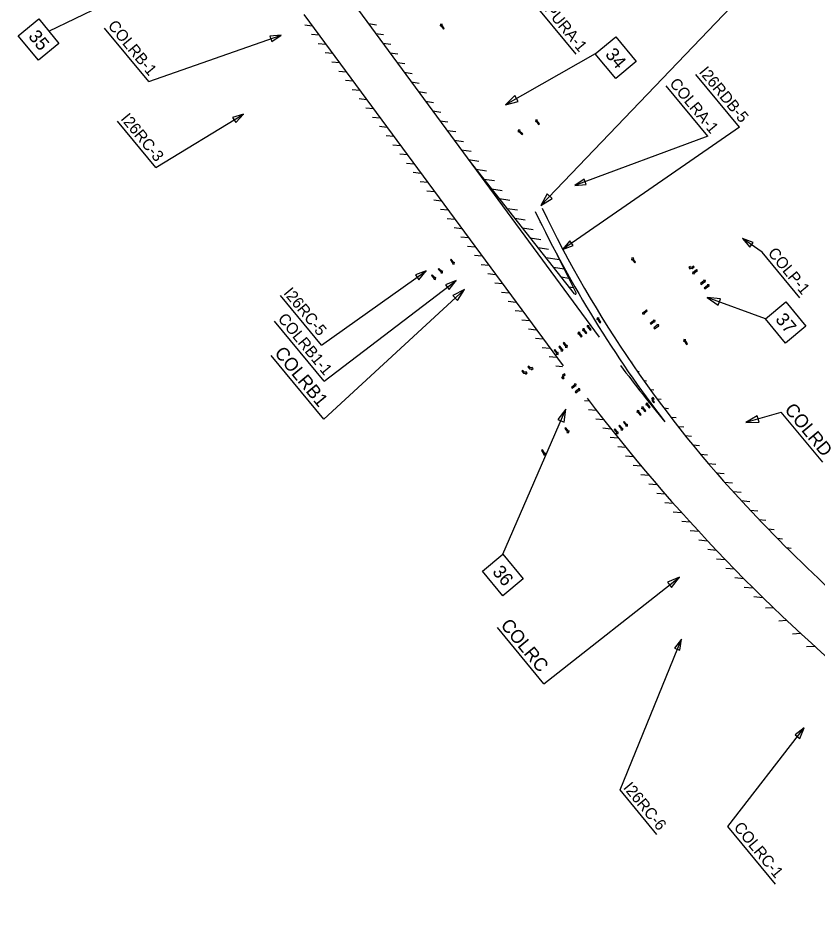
# Model space of a CAD drawing. Extents: x 1966356 to 1974207, y 790684 to 800034.
# Drawn here: x 1970016 to 1971705, y 794729 to 796663 of the extents above; entities that cross this region are included whole.
import ezdxf

# ---------------------------------------------------------------- set-up
doc = ezdxf.new("R2010")
doc.units = 0
doc.layers.add('RD_PD_ALT5_LnLine', color=7, linetype='Continuous')
doc.layers.add('RD_TX_RoadID', color=7, linetype='Continuous')

msp = doc.modelspace()

# ---------------------------------------------------------------- linework, layer by layer
at = {"layer": 'RD_PD_ALT5_LnLine'}
for p, q in [((1970581.2, 796888.4), (1971243.9, 795989.5)), ((1970619.8, 796670.9), (1971167.2, 795928.4)), ((1970621.4, 796648.6), (1970637.4, 796647)), ((1970756, 796651.3), (1970772.8, 796648.8)), ((1970635.7, 796629.1), (1970651.7, 796627.6)), ((1970771.1, 796630.8), (1970787.9, 796628.3)), ((1970650, 796609.7), (1970666.1, 796608.1)), ((1970786.2, 796610.4), (1970803, 796607.8)), ((1970664.4, 796590.2), (1970680.4, 796588.7)), ((1970801.3, 796589.9), (1970818.1, 796587.3)), ((1970678.7, 796570.8), (1970694.8, 796569.2)), ((1970693.1, 796551.3), (1970709.1, 796549.8)), ((1970816.4, 796569.4), (1970833.2, 796566.8)), ((1970707.4, 796531.8), (1970723.4, 796530.3)), ((1970831.5, 796548.9), (1970848.3, 796546.3)), ((1970846.6, 796528.4), (1970863.4, 796525.9)), ((1970721.8, 796512.4), (1970737.8, 796510.9)), ((1970861.7, 796507.9), (1970878.5, 796505.4)), ((1970736.1, 796492.9), (1970752.1, 796491.4)), ((1970876.8, 796487.4), (1970893.6, 796484.9)), ((1970750.4, 796473.5), (1970766.5, 796471.9)), ((1970891.9, 796466.9), (1970908.7, 796464.4)), ((1970764.8, 796454), (1970780.8, 796452.5)), ((1970907, 796446.4), (1970924.1, 796443.9)), ((1970779.1, 796434.6), (1970795.2, 796433)), ((1970922.1, 796425.9), (1970940.4, 796423.2)), ((1970793.5, 796415.1), (1970809.5, 796413.6)), ((1970937.2, 796405.5), (1970956.8, 796402.5)), ((1970807.8, 796395.7), (1970823.8, 796394.1)), ((1970952.3, 796385), (1970973.1, 796381.8)), ((1970822.1, 796376.2), (1970838.2, 796374.7)), ((1970967.5, 796364.5), (1970989.4, 796361.2)), ((1971191.7, 796080.5), (1970968.6, 796363)), ((1970836.5, 796356.8), (1970852.5, 796355.2)), ((1970983.7, 796343.8), (1971005.8, 796340.5)), ((1970850.8, 796337.3), (1970866.9, 796335.8)), ((1971000, 796323.1), (1971022.1, 796319.8)), ((1970865.2, 796317.8), (1970881.2, 796316.3)), ((1971016.4, 796302.5), (1971038.4, 796299.1)), ((1970879.5, 796298.4), (1970895.6, 796296.9)), ((1971032.7, 796281.8), (1971054.8, 796278.5)), ((1970893.9, 796278.9), (1970909.9, 796277.4)), ((1970908.2, 796259.5), (1970924.2, 796257.9)), ((1971049, 796261.1), (1971071.1, 796257.8)), ((1970922.5, 796240), (1970938.6, 796238.5)), ((1971065.4, 796240.4), (1971087.4, 796237.1)), ((1971118.4, 796232.4), (1971119.4, 796232.3)), ((1970936.9, 796220.6), (1970952.9, 796219)), ((1971081.7, 796219.8), (1971103.8, 796216.4)), ((1970951.2, 796201.1), (1970967.3, 796199.6)), ((1971098, 796199.1), (1971120.1, 796195.7)), ((1970965.6, 796181.7), (1970981.6, 796180.1)), ((1971114.4, 796178.4), (1971136.4, 796175.1)), ((1970979.9, 796162.2), (1970995.9, 796160.7)), ((1971130.7, 796157.7), (1971159.8, 796153.3)), ((1971195.1, 796082.7), (1971154.9, 796163.2)), ((1970994.2, 796142.8), (1971010.3, 796141.2)), ((1971147, 796137.1), (1971169.6, 796133.6)), ((1971008.6, 796123.3), (1971024.6, 796121.8)), ((1971163.4, 796116.4), (1971179.4, 796113.9)), ((1971022.9, 796103.8), (1971039, 796102.3)), ((1971179.7, 796095.7), (1971189.3, 796094.3)), ((1971037.3, 796084.4), (1971053.3, 796082.9)), ((1971051.6, 796064.9), (1971067.7, 796063.4)), ((1971066, 796045.5), (1971082, 796043.9)), ((1971080.3, 796026), (1971096.3, 796024.5)), ((1971094.6, 796006.6), (1971110.7, 796005)), ((1971109, 795987.1), (1971125, 795985.6)), ((1971123.3, 795967.7), (1971139.4, 795966.1)), ((1971137.7, 795948.2), (1971153.7, 795946.7)), ((1971310.7, 795936.5), (1971313.5, 795936.2)), ((1971152, 795928.8), (1971165.9, 795927.4)), ((1971324, 795917.2), (1971328.4, 795916.8)), ((1971337.6, 795897.8), (1971343.5, 795897.3)), ((1971351.5, 795878.5), (1971358.8, 795877.8)), ((1971212.4, 795855.5), (1971222.4, 795854.5)), ((1971365.7, 795859.1), (1971374.4, 795858.3)), ((1971221, 795836.5), (1971237.4, 795835)), ((1971380.1, 795839.7), (1971390.2, 795838.8)), ((1971236.2, 795817), (1971252.6, 795815.4)), ((1971394.9, 795820.3), (1971406.2, 795819.2)), ((1971251.5, 795797.5), (1971268.1, 795795.9)), ((1971410.1, 795800.8), (1971422.4, 795799.7)), ((1971267.1, 795777.9), (1971283.8, 795776.3)), ((1971425.5, 795781.3), (1971438.9, 795780.1)), ((1971441.3, 795761.8), (1971455.7, 795760.5)), ((1971282.9, 795758.3), (1971299.7, 795756.7)), ((1971457.5, 795742.2), (1971472.7, 795740.8)), ((1971298.9, 795738.7), (1971315.8, 795737.1)), ((1971474, 795722.6), (1971490, 795721.2)), ((1971315.2, 795719), (1971332.2, 795717.4)), ((1971490.9, 795703), (1971507.5, 795701.5)), ((1971331.7, 795699.4), (1971348.8, 795697.7)), ((1971508.1, 795683.3), (1971525.4, 795681.8)), ((1971348.4, 795679.7), (1971365.7, 795678)), ((1971525.8, 795663.6), (1971543.4, 795662)), ((1971365.4, 795660), (1971382.8, 795658.3)), ((1971543.9, 795643.9), (1971561.7, 795642.3)), ((1971382.7, 795640.3), (1971400.2, 795638.6)), ((1971562.4, 795624.1), (1971578.7, 795622.6)), ((1971400.2, 795620.5), (1971417.8, 795618.8)), ((1971581.2, 795604.3), (1971595.9, 795603)), ((1971418, 795600.7), (1971435.7, 795599)), ((1971436, 795580.9), (1971453.9, 795579.2)), ((1971600.4, 795584.5), (1971613.3, 795583.3)), ((1971454.3, 795561.1), (1971472.3, 795559.3)), ((1971619.8, 795564.6), (1971631, 795563.6)), ((1971472.9, 795541.2), (1971491.1, 795539.5)), ((1971639.6, 795544.7), (1971649.1, 795543.9)), ((1971491.8, 795521.3), (1971510.1, 795519.6)), ((1971659.7, 795524.8), (1971660, 795524.8)), ((1971511, 795501.4), (1971529.5, 795499.6)), ((1971530.5, 795481.4), (1971549.1, 795479.7)), ((1971550.3, 795461.5), (1971569.1, 795459.7)), ((1971570.4, 795441.5), (1971589.5, 795439.6)), ((1971595, 795417.5), (1971611.2, 795418.5)), ((1971623.4, 795390.2), (1971639.8, 795391.2)), ((1971652.4, 795362.9), (1971669, 795363.9)), ((1971682, 795335.7), (1971698.7, 795336.7))]:
    msp.add_line(p, q, dxfattribs=at)
for points in [[(1970914.3, 796639.9), (1970916.2, 796641.2), (1970911.1, 796648.8), (1970912.4, 796649.7), (1970908.5, 796650.5), (1970907.7, 796646.5), (1970909.1, 796647.4)], [(1971115.6, 796438), (1971117.5, 796439.4), (1971112.1, 796446.8), (1971113.5, 796447.8), (1971109.5, 796448.4), (1971108.9, 796444.5), (1971110.2, 796445.4)], [(1971080.5, 796417.2), (1971082.1, 796418.9), (1971075.4, 796425.2), (1971076.5, 796426.4), (1971072.5, 796426.2), (1971072.7, 796422.2), (1971073.8, 796423.4)], [(1970931.1, 796153.7), (1970929.2, 796152.3), (1970934.7, 796144.9), (1970933.4, 796144), (1970937.3, 796143.4), (1970937.9, 796147.3), (1970936.6, 796146.4)], [(1971318.7, 796146), (1971320.7, 796147.4), (1971315.5, 796154.9), (1971316.8, 796155.8), (1971312.9, 796156.5), (1971312.2, 796152.6), (1971313.5, 796153.5)], [(1970904.8, 796134.3), (1970903.1, 796132.5), (1970909.9, 796126.3), (1970908.8, 796125.1), (1970912.7, 796125.3), (1970912.6, 796129.3), (1970911.5, 796128.1)], [(1971444.4, 796137.4), (1971442.9, 796139.3), (1971439.5, 796136.6), (1971436.1, 796137), (1971436.3, 796138.6), (1971433.1, 796136.1), (1971435.6, 796133), (1971435.8, 796134.6), (1971440.3, 796134.1)], [(1971451.1, 796129.8), (1971449.6, 796131.7), (1971442.4, 796126), (1971441.4, 796127.3), (1971440.9, 796123.3), (1971444.9, 796122.8), (1971443.9, 796124.1)], [(1970890.9, 796121.1), (1970889.1, 796119.5), (1970895.2, 796112.6), (1970894, 796111.5), (1970898, 796111.3), (1970898.2, 796115.3), (1970897, 796114.2)], [(1971457.9, 796102.5), (1971459.4, 796100.6), (1971466.6, 796106.4), (1971467.6, 796105.1), (1971468.1, 796109.1), (1971464.1, 796109.5), (1971465.1, 796108.2)], [(1971465.6, 796092.9), (1971467.1, 796091), (1971474.3, 796096.7), (1971475.3, 796095.4), (1971475.8, 796099.4), (1971471.8, 796099.9), (1971472.8, 796098.6)], [(1971244.8, 796019.3), (1971246.9, 796020.6), (1971242.1, 796028.4), (1971243.4, 796029.2), (1971239.5, 796030.2), (1971238.6, 796026.3), (1971240, 796027.1)], [(1971345.3, 796044.7), (1971343.8, 796046.6), (1971336.7, 796040.9), (1971335.6, 796042.2), (1971335.2, 796038.2), (1971339.2, 796037.7), (1971338.2, 796039)], [(1971224.8, 796003.7), (1971226.7, 796005.2), (1971221.1, 796012.4), (1971222.3, 796013.4), (1971218.4, 796013.9), (1971217.9, 796010), (1971219.2, 796011)], [(1971351.4, 796018.2), (1971352.9, 796016.3), (1971360.1, 796022), (1971361.1, 796020.7), (1971361.6, 796024.7), (1971357.6, 796025.2), (1971358.6, 796023.9)], [(1971359.3, 796008.7), (1971360.8, 796006.8), (1971368, 796012.5), (1971369, 796011.3), (1971369.4, 796015.2), (1971365.5, 796015.7), (1971366.5, 796014.4)], [(1971205.5, 795989.5), (1971207.4, 795991), (1971201.8, 795998.2), (1971203.1, 795999.2), (1971199.1, 795999.7), (1971198.6, 795995.8), (1971199.9, 795996.8)], [(1971215.4, 795996.8), (1971217.3, 795998.3), (1971211.7, 796005.5), (1971212.9, 796006.5), (1971209, 796007), (1971208.5, 796003), (1971209.8, 796004)], [(1971169.7, 795977.9), (1971167.8, 795976.4), (1971173.3, 795969.1), (1971172, 795968.1), (1971176, 795967.6), (1971176.5, 795971.6), (1971175.2, 795970.6)], [(1971428.4, 795973.7), (1971430.4, 795975), (1971425.2, 795982.6), (1971426.5, 795983.5), (1971422.6, 795984.2), (1971421.8, 795980.3), (1971423.2, 795981.2)], [(1971150.2, 795963.2), (1971148.3, 795961.7), (1971153.9, 795954.4), (1971152.6, 795953.5), (1971156.6, 795952.9), (1971157.1, 795956.9), (1971155.8, 795955.9)], [(1971160.2, 795970.2), (1971158.3, 795968.8), (1971163.9, 795961.5), (1971162.6, 795960.5), (1971166.5, 795960), (1971167.1, 795963.9), (1971165.8, 795962.9)], [(1971080.5, 795917.3), (1971083.8, 795913.1), (1971088.3, 795912.6), (1971088.1, 795911), (1971091.2, 795913.5), (1971088.7, 795916.6), (1971088.6, 795915), (1971085.1, 795915.4), (1971082.4, 795918.8)], [(1971093, 795926.7), (1971096.4, 795922.5), (1971100.8, 795922), (1971100.6, 795920.4), (1971103.8, 795922.9), (1971101.3, 795926), (1971101.1, 795924.4), (1971097.6, 795924.8), (1971094.9, 795928.2)], [(1971170.4, 795911.6), (1971166.2, 795908.3), (1971165.7, 795903.8), (1971164.1, 795904), (1971166.6, 795900.9), (1971169.7, 795903.4), (1971168.1, 795903.6), (1971168.5, 795907), (1971171.9, 795909.8)], [(1971184.9, 795883.1), (1971186.4, 795881.2), (1971193.6, 795887), (1971194.6, 795885.7), (1971195, 795889.7), (1971191.1, 795890.1), (1971192.1, 795888.8)], [(1971192.8, 795873.6), (1971194.3, 795871.8), (1971201.4, 795877.5), (1971202.5, 795876.2), (1971202.9, 795880.2), (1971198.9, 795880.6), (1971199.9, 795879.4)], [(1971358.8, 795850.3), (1971360.7, 795851.8), (1971358, 795855.2), (1971358.4, 795858.7), (1971360, 795858.5), (1971357.6, 795861.6), (1971354.4, 795859.1), (1971356, 795858.9), (1971355.5, 795854.5)], [(1971340.1, 795832), (1971342, 795833.5), (1971336.3, 795840.6), (1971337.5, 795841.7), (1971333.6, 795842.1), (1971333.1, 795838.1), (1971334.4, 795839.1)], [(1971349.5, 795839.8), (1971351.4, 795841.3), (1971345.6, 795848.4), (1971346.9, 795849.4), (1971342.9, 795849.9), (1971342.5, 795845.9), (1971343.8, 795846.9)], [(1971330.4, 795824.2), (1971332.3, 795825.7), (1971326.6, 795832.9), (1971327.8, 795833.9), (1971323.9, 795834.4), (1971323.4, 795830.4), (1971324.7, 795831.4)], [(1971172.9, 795797.8), (1971171.1, 795796.3), (1971176.8, 795789.1), (1971175.5, 795788.1), (1971179.5, 795787.6), (1971179.9, 795791.6), (1971178.7, 795790.6)], [(1971286.8, 795803.5), (1971284.9, 795802), (1971290.7, 795794.8), (1971289.4, 795793.8), (1971293.4, 795793.4), (1971293.8, 795797.3), (1971292.6, 795796.3)], [(1971296.6, 795811.3), (1971294.7, 795809.8), (1971300.4, 795802.6), (1971299.2, 795801.6), (1971303.2, 795801.2), (1971303.6, 795805.2), (1971302.3, 795804.1)], [(1971277, 795795.7), (1971275.2, 795794.2), (1971280.9, 795787), (1971279.6, 795786), (1971283.6, 795785.5), (1971284, 795789.5), (1971282.8, 795788.5)], [(1971123.8, 795751.1), (1971121.7, 795749.9), (1971126.5, 795742), (1971125.1, 795741.2), (1971128.9, 795740.2), (1971129.9, 795744.1), (1971128.5, 795743.3)]]:
    msp.add_lwpolyline(points, close=True, dxfattribs=at)
for centre, radius, start, end in [((1973392.6, 797356.4), 2520, 205.75, 223.1722), ((1973392.6, 797356.4), 2536, 205.75, 217.5539), ((1971193.3, 796081.7), 2, 216.3977, 30.0977), ((1974296, 798203.9), 3770.7, 217.1065, 219.3969), ((1974296, 798203.9), 3868.7, 217.2903, 243.9112), ((1974296, 798203.9), 3758.7, 223.1722, 227.2191)]:
    msp.add_arc(centre, radius, start, end, dxfattribs=at)
at = {"layer": 'RD_TX_RoadID'}
for p, q in [((1971194.9, 796587), (1971065.8, 796743.3)), ((1970292, 796528.9), (1970198.5, 796642.1)), ((1971539.8, 796433), (1971447.9, 796544.2)), ((1971473.3, 796413.4), (1971385.5, 796519.9)), ((1970306.9, 796347.3), (1970225.8, 796445.4)), ((1971667.5, 796072.2), (1971587.7, 796168.8)), ((1970656.6, 795972.5), (1970569.9, 796077.4)), ((1970662.5, 795896.3), (1970557.8, 796023.2)), ((1970661.9, 795815.8), (1970550.5, 795950.7)), ((1971716.1, 795724.9), (1971628.4, 795831.1)), ((1971126.8, 795256.9), (1971028.5, 795375.8)), ((1971365.4, 794938.9), (1971287.8, 795032.9)), ((1971616, 794834.1), (1971515.6, 794955.7))]:
    msp.add_line(p, q, dxfattribs=at)
for points in [[(1970080.6, 796635.4), (1970303.3, 796743.1)], [(1971554.2, 796720.6), (1971120, 796267.5)], [(1970292, 796528.9), (1970571.4, 796626.9)], [(1971235.3, 796587.7), (1971045.5, 796479.6)], [(1970306.9, 796347.3), (1970492, 796459.9)], [(1971539.8, 796433), (1971166.3, 796174.4)], [(1971473.3, 796413.4), (1971192.3, 796309.3)], [(1971587.7, 796168.8), (1971546.4, 796197.4)], [(1970656.6, 795972.5), (1970878.2, 796129)], [(1970662.5, 795896.3), (1970941.1, 796108.9)], [(1970661.9, 795815.8), (1970958.8, 796090)], [(1971594.8, 796028), (1971471.9, 796072.8)], [(1971040, 795530.6), (1971173.5, 795837.3)], [(1971627.5, 795830.4), (1971553.7, 795808.9)], [(1971126.8, 795256.9), (1971413.6, 795482.6)], [(1971287.8, 795032.9), (1971417.3, 795351.7)], [(1971515.6, 794955.7), (1971677.1, 795163.9)]]:
    msp.add_lwpolyline(points, dxfattribs=at)
for points in [[(1970059.2, 796661.3), (1970102, 796609.5), (1970058.9, 796573.9), (1970016.1, 796625.7)], [(1970551.6, 796613.4), (1970571.4, 796626.9), (1970547.5, 796625.1)], [(1971278.5, 796623.4), (1971321.6, 796571.1), (1971278.5, 796535.4), (1971235.3, 796587.7)], [(1971065.4, 796499.3), (1971045.5, 796479.6), (1971072.6, 796486.7)], [(1970475.5, 796442.6), (1970492, 796459.9), (1970469, 796453.2)], [(1971211.8, 796323.2), (1971192.3, 796309.3), (1971216.2, 796311.6)], [(1971133.5, 796292), (1971120, 796267.5), (1971144, 796282)], [(1971181.8, 796192.7), (1971166.3, 796174.4), (1971188.9, 796182.5)], [(1971569, 796189.3), (1971546.4, 796197.4), (1971561.9, 796179.1)], [(1970862.8, 796110.6), (1970878.2, 796129), (1970855.6, 796120.7)], [(1970926.4, 796089.9), (1970941.1, 796108.9), (1970918.9, 796099.8)], [(1970943.9, 796066.3), (1970958.8, 796090), (1970934.1, 796077)], [(1971499.8, 796070.3), (1971471.9, 796072.8), (1971494.9, 796056.7)], [(1971638, 796063.7), (1971680.3, 796012.4), (1971637.1, 795976.8), (1971594.8, 796028)], [(1971169.4, 795809.7), (1971173.5, 795837.3), (1971156.1, 795815.4)], [(1971577.7, 795823.4), (1971553.7, 795808.9), (1971581.7, 795809.5)], [(1971040, 795530.6), (1971083, 795478.6), (1971039.8, 795442.9), (1970996.8, 795494.9)], [(1971396.8, 795460.2), (1971413.6, 795482.6), (1971387.9, 795471.6)], [(1971414.3, 795327.9), (1971417.3, 795351.7), (1971402.8, 795332.6)], [(1971667.8, 795141.8), (1971677.1, 795163.9), (1971658, 795149.4)]]:
    msp.add_lwpolyline(points, close=True, dxfattribs=at)

# ---------------------------------------------------------------- texts
for s, height, p in [('COLSPURA-1', 24, (1971071.2, 796747.7)), ('COLRB-1 ', 24, (1970203.9, 796646.6)), ('35', 28, (1970035.8, 796623.8)), ('34', 28, (1971255, 796585.8)), ('I26RDB-5', 24, (1971453.3, 796548.7)), ('COLRA-1', 24, (1971390.9, 796524.3)), ('I26RC-3 ', 24, (1970231.2, 796449.9)), (' COLP-1', 24, (1971593.1, 796173.3)), ('I26RC-5  ', 24, (1970575.3, 796081.9)), ('COLRB1-1 ', 24, (1970563.2, 796027.6)), ('37', 28, (1971614.5, 796026.1)), ('COLRB1  ', 28, (1970555.9, 795955.1)), ('COLRD', 28, (1971633.8, 795835.6)), ('36', 28, (1971016.5, 795493)), ('COLRC  ', 28, (1971033.9, 795380.3)), ('I26RC-6', 24, (1971293.2, 795037.3)), (' COLRC-1 ', 24, (1971521, 794960.2))]:
    msp.add_text(s, height=height, rotation=309.5517, dxfattribs=at).set_placement(p)

doc.saveas('drawing.dxf')
